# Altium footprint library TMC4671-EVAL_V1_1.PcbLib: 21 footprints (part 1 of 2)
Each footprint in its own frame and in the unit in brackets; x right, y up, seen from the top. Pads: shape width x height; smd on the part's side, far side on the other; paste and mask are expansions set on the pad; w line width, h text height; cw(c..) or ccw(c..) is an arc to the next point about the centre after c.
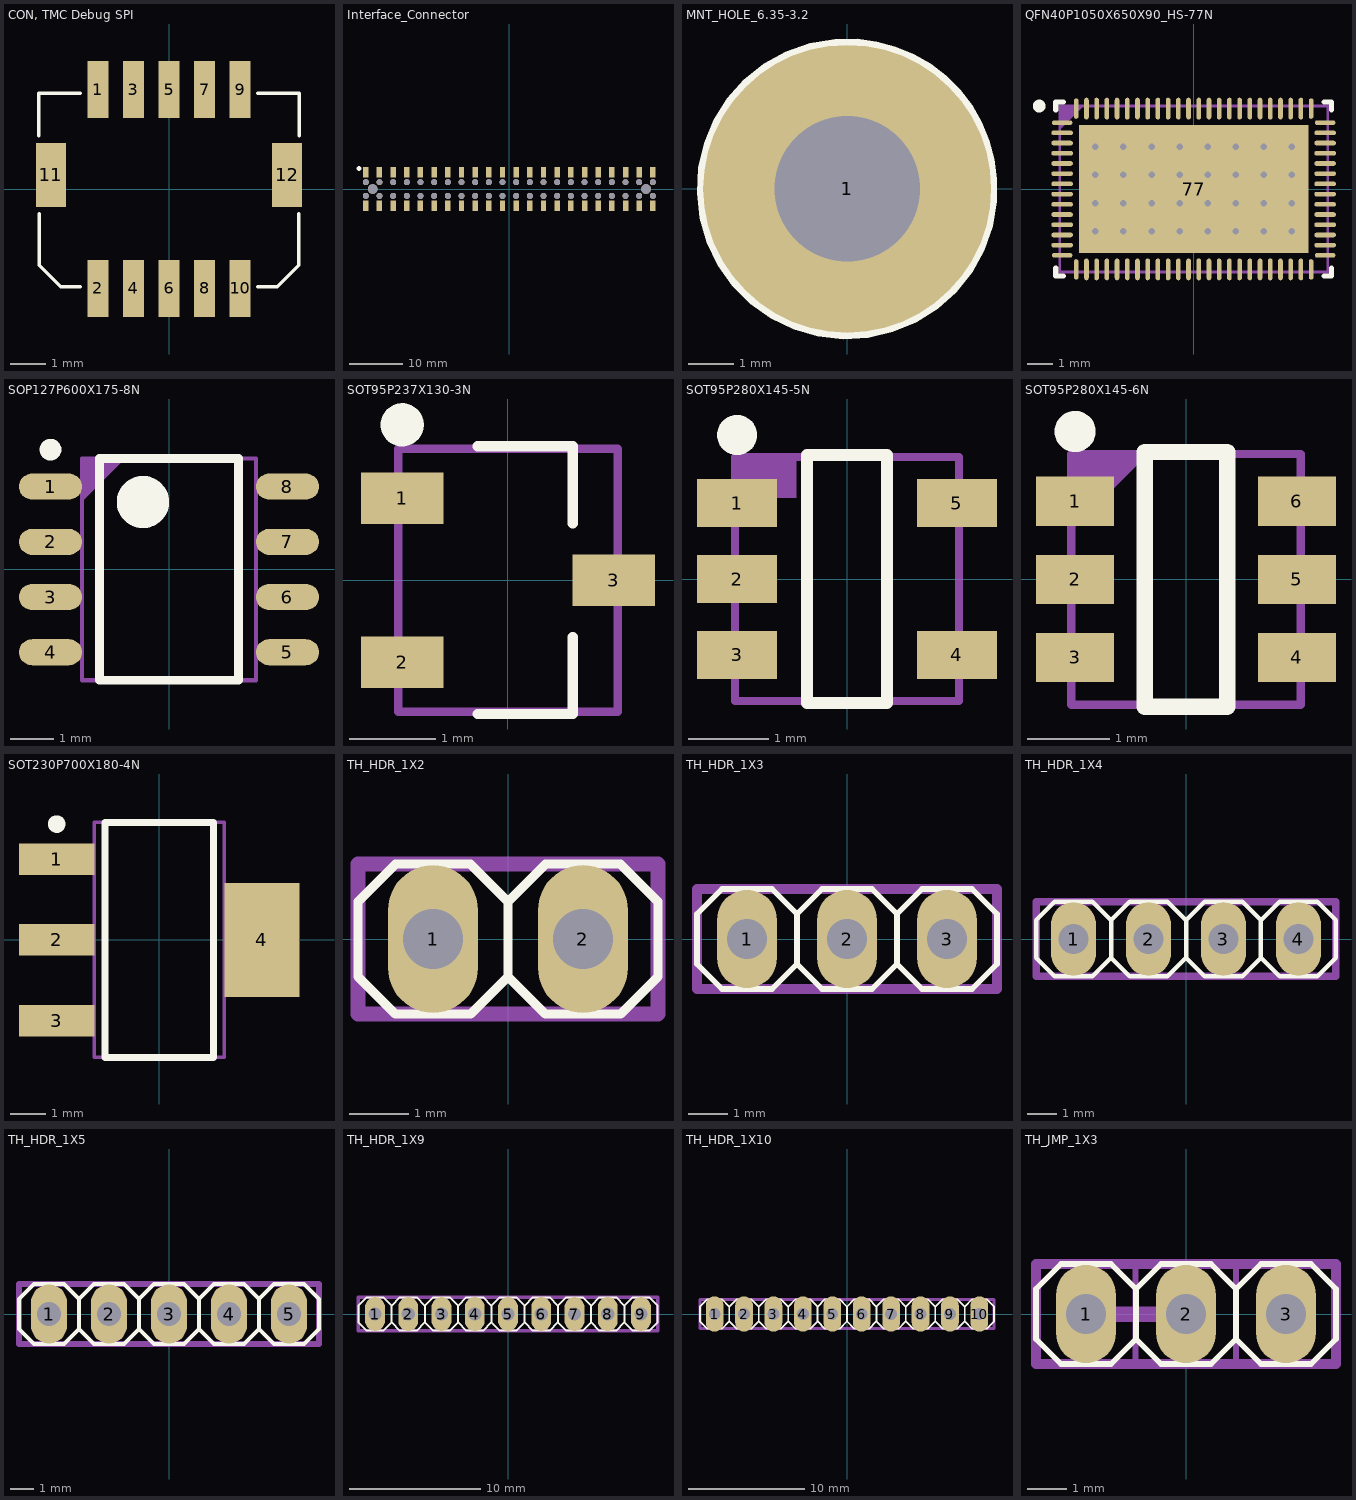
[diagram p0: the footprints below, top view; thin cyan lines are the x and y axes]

## CON, TMC Debug SPI [mm]
pads (12):
  rect 0.6x1.6 smd: 1(-2,2.8) 2(-2,-2.8) 3(-1,2.8) 4(-1,-2.8) 5(0,2.8) 6(0,-2.8) 7(1,2.8) 8(1,-2.8) 9(2,2.8) 10(2,-2.8)
  rect 0.85x1.8 smd: 11(-3.325,0.4) 12(3.325,0.4)
Top Overlay:
  lines w0.1: -3.675,1.5 -3.675,2.7 -2.5,2.7 ; -3.65,-0.7 -3.65,-2.15 -3.05,-2.75 -2.5,-2.75 ; 2.5,-2.75 3.05,-2.75 3.65,-2.15 3.65,-0.7 ; 2.5,2.7 3.675,2.7 3.675,1.5
TopAsm:
  text ".Designator" at -2.589,-0.401 h1
3D body "DF20F-10DP-1V.stp": height 4.6, standoff 0, extent -3.65,-3.225 3.65,3.175

## Interface_Connector [mil]
pads (90):
  rect 40x75 smd: 1(-1050,122.72) 2(-1050,-122.72) 3(-950,122.72) 4(-950,-122.72) 5(-850,122.72) 6(-850,-122.72) 7(-750,122.72) 8(-750,-122.72) 9(-650,122.72) 10(-650,-122.72) 11(-550,122.72) 12(-550,-122.72) 13(-450,122.72) 14(-450,-122.72) 15(-350,122.72) 16(-350,-122.72) 17(-250,122.72) 18(-250,-122.72) 19(-150,122.72) 20(-150,-122.72) 21(-50,122.72) 22(-50,-122.72) 23(50,122.72) 24(50,-122.72) 25(150,122.72) 26(150,-122.72) 27(250,122.72) 28(250,-122.72) 29(350,122.72) 30(350,-122.72) 31(450,122.72) 32(450,-122.72) 33(550,122.72) 34(550,-122.72) 35(650,122.72) 36(650,-122.72) 37(750,122.72) 38(750,-122.72) 39(850,122.72) 40(850,-122.72) 41(950,122.72) 42(950,-122.72) 43(1050,122.72) 44(1050,-122.72)
  round 44 hole 44: HOLE(-1050,-50.28) HOLE(-1050,49.72) HOLE(-950,-50.28) HOLE(-950,49.72) HOLE(-850,-50.28) HOLE(-850,49.72) HOLE(-750,-50.28) HOLE(-750,49.72) HOLE(-650,-50.28) HOLE(-650,49.72) HOLE(-550,-50.28) HOLE(-550,49.72) HOLE(-450,-50.28) HOLE(-450,49.72) HOLE(-350,-50.28) HOLE(-350,49.72) HOLE(-250,-50.28) HOLE(-250,49.72) HOLE(-150,-50.28) HOLE(-150,49.72) HOLE(-50,-50.28) HOLE(-50,49.72) HOLE(50,-50.28) HOLE(50,49.72) HOLE(150,-50.28) HOLE(150,49.72) HOLE(250,-50.28) HOLE(250,49.72) HOLE(350,-50.28) HOLE(350,49.72) HOLE(450,-50.28) HOLE(450,49.72) HOLE(550,-50.28) HOLE(550,49.72) HOLE(650,-50.28) HOLE(650,49.72) HOLE(750,-50.28) HOLE(750,49.72) HOLE(850,-50.28) HOLE(850,49.72) HOLE(950,-50.28) HOLE(950,49.72) HOLE(1050,-50.28) HOLE(1050,49.72)
  round 71 hole 71: HOLE(-1000,-0.28) HOLE(1000,-0.28)
Top Overlay:
  circle w19.68: c-1100,150 r7.07
TopAsm:
  text ".Designator" at -155,-40 h118.11
3D body "HLE-122-02-L-DV.stp": height 143.51, standoff -0.49, extent -1100,-129.49 1100,129.51

## MNT_HOLE_6.35-3.2 [mm]
pads (1):
  round 6.35 hole 3.2: 1(0,0)
Top Overlay:
  pour cut-out: 0,3.302 -0.279,3.302 -0.828,3.209 -1.354,3.025 -1.841,2.755 -2.277,2.408 -2.648,1.993 -2.944,1.521 -3.157,1.006 -3.281,0.463 -3.312,-0.093 -3.25,-0.647 -3.096,-1.182 -2.854,-1.684 -2.532,-2.138 -2.138,-2.532 -1.684,-2.854 -1.182,-3.096 -0.646,-3.25 -0.093,-3.312 0.463,-3.281 1.006,-3.157 1.521,-2.944 1.993,-2.648 2.408,-2.277 2.755,-1.841 3.025,-1.353 3.209,-0.828 3.302,-0.279 3.302,0 3.302,0.216 3.246,0.646 3.133,1.064 2.968,1.464 2.751,1.838 2.488,2.182 2.182,2.488 1.838,2.751 1.464,2.968 1.064,3.134 0.646,3.246 0.216,3.302
Bottom Overlay:
  pour cut-out: 0,3.302 -0.279,3.302 -0.828,3.209 -1.354,3.025 -1.841,2.755 -2.277,2.408 -2.648,1.993 -2.944,1.521 -3.157,1.006 -3.281,0.463 -3.312,-0.093 -3.25,-0.647 -3.096,-1.182 -2.854,-1.684 -2.532,-2.138 -2.138,-2.532 -1.684,-2.854 -1.182,-3.096 -0.646,-3.25 -0.093,-3.312 0.463,-3.281 1.006,-3.157 1.521,-2.944 1.993,-2.648 2.408,-2.277 2.755,-1.841 3.025,-1.353 3.209,-0.828 3.302,-0.279 3.302,0 3.302,0.216 3.246,0.646 3.133,1.064 2.968,1.464 2.751,1.838 2.488,2.182 2.182,2.488 1.838,2.751 1.464,2.968 1.064,3.134 0.646,3.246 0.216,3.302

## QFN40P1050X650X90_HS-77N [mm] "QFN, 76-Leads, Body 10,50x6,50mm, Pitch 0,40mm, Thermal Pad 9,00x5,00mm, IPC Medium Density"
height 0.9
pads (77):
  oval 0.8x0.182 smd mask+0.051: 1(-5.15,2.6) 14(-5.15,-2.6) 39(5.15,-2.6) 52(5.15,2.6)
  oval 0.85x0.182 smd mask+0.051: 2(-5.15,2.2) 3(-5.15,1.8) 4(-5.15,1.4) 5(-5.15,1) 6(-5.15,0.6) 7(-5.15,0.2) 8(-5.15,-0.2) 9(-5.15,-0.6) 10(-5.15,-1) 11(-5.15,-1.4) 12(-5.15,-1.8) 13(-5.15,-2.2) 40(5.15,-2.2) 41(5.15,-1.8) 42(5.15,-1.4) 43(5.15,-1) 44(5.15,-0.6) 45(5.15,-0.2) 46(5.15,0.2) 47(5.15,0.6) 48(5.15,1) 49(5.15,1.4) 50(5.15,1.8) 51(5.15,2.2)
  oval 0.182x0.8 smd mask+0.051: 15(-4.6,-3.15) 38(4.6,-3.15) 53(4.6,3.15) 76(-4.6,3.15)
  oval 0.182x0.85 smd mask+0.051: 16(-4.2,-3.15) 17(-3.8,-3.15) 18(-3.4,-3.15) 19(-3,-3.15) 20(-2.6,-3.15) 21(-2.2,-3.15) 22(-1.8,-3.15) 23(-1.4,-3.15) 24(-1,-3.15) 25(-0.6,-3.15) 26(-0.2,-3.15) 27(0.2,-3.15) 28(0.6,-3.15) 29(1,-3.15) 30(1.4,-3.15) 31(1.8,-3.15) 32(2.2,-3.15) 33(2.6,-3.15) 34(3,-3.15) 35(3.4,-3.15) 36(3.8,-3.15) 37(4.2,-3.15) 54(4.2,3.15) 55(3.8,3.15) 56(3.4,3.15) 57(3,3.15) 58(2.6,3.15) 59(2.2,3.15) 60(1.8,3.15) 61(1.4,3.15) 62(1,3.15) 63(0.6,3.15) 64(0.2,3.15) 65(-0.2,3.15) 66(-0.6,3.15) 67(-1,3.15) 68(-1.4,3.15) 69(-1.8,3.15) 70(-2.2,3.15) 71(-2.6,3.15) 72(-3,3.15) 73(-3.4,3.15) 74(-3.8,3.15) 75(-4.2,3.15)
  rect 9x5 smd: 77(0,0)
via -3.85,1.65 diameter 0.61 hole 0.254
via -2.75,1.65 diameter 0.61 hole 0.254
via -1.65,1.65 diameter 0.61 hole 0.254
via -0.55,1.65 diameter 0.61 hole 0.254
via 0.55,1.65 diameter 0.61 hole 0.254
via 1.65,1.65 diameter 0.61 hole 0.254
via 2.75,1.65 diameter 0.61 hole 0.254
via 3.85,1.65 diameter 0.61 hole 0.254
via -3.85,0.55 diameter 0.61 hole 0.254
via -2.75,0.55 diameter 0.61 hole 0.254
via -1.65,0.55 diameter 0.61 hole 0.254
via -0.55,0.55 diameter 0.61 hole 0.254
via 0.55,0.55 diameter 0.61 hole 0.254
via 1.65,0.55 diameter 0.61 hole 0.254
via 2.75,0.55 diameter 0.61 hole 0.254
via 3.85,0.55 diameter 0.61 hole 0.254
via -3.85,-0.55 diameter 0.61 hole 0.254
via -2.75,-0.55 diameter 0.61 hole 0.254
via -1.65,-0.55 diameter 0.61 hole 0.254
via -0.55,-0.55 diameter 0.61 hole 0.254
via 0.55,-0.55 diameter 0.61 hole 0.254
via 1.65,-0.55 diameter 0.61 hole 0.254
via 2.75,-0.55 diameter 0.61 hole 0.254
via 3.85,-0.55 diameter 0.61 hole 0.254
via -3.85,-1.65 diameter 0.61 hole 0.254
via -2.75,-1.65 diameter 0.61 hole 0.254
via -1.65,-1.65 diameter 0.61 hole 0.254
via -0.55,-1.65 diameter 0.61 hole 0.254
via 0.55,-1.65 diameter 0.61 hole 0.254
via 1.65,-1.65 diameter 0.61 hole 0.254
via 2.75,-1.65 diameter 0.61 hole 0.254
via 3.85,-1.65 diameter 0.61 hole 0.254
Top Overlay:
  circle w0.25: c-6.05,3.25 r0.125
  lines w0.2: -5.4,-3.1 -5.4,-3.4 -5.1,-3.4 ; -5.4,3.1 -5.4,3.4 -5.1,3.4 ; 5.1,-3.4 5.4,-3.4 5.4,-3.1 ; 5.1,3.4 5.4,3.4 5.4,3.1
TopAsm:
  region: -5.25,3.25 -5.25,2.318 -4.318,3.25
  lines w0.1: -5.25,-3.25 5.25,-3.25 5.25,3.25 -5.25,3.25 -5.25,-3.25
  text ".Designator" at -3.014,-0.451 h1
3D body "QFN40P1050X650X90_HS-77N.step": height 0.9, standoff 0, extent -5.251,-3.251 5.251,3.251

## SOP127P600X175-8N [mm] "SOP, 8-Leads, Body 4,92x3,90mm, Pitch 1,27mm, IPC Medium Density"
height 1.75
pads (8):
  oval 1.45x0.6 smd: 1(-2.725,1.905) 2(-2.725,0.635) 3(-2.725,-0.635) 4(-2.725,-1.905) 5(2.725,-1.905) 6(2.725,-0.635) 7(2.725,0.635) 8(2.725,1.905)
Top Overlay:
  circle w0.25: c-2.725,2.755 r0.125
  circle w0.6: c-0.6,1.55 r0.3
  lines w0.2: -1.6,-2.55 -1.6,2.55 1.6,2.55 1.6,-2.55 -1.6,-2.55
TopAsm:
  region: -2,2.55 -2,1.566 -1.016,2.55
  lines w0.1: -2,-2.55 2,-2.55 2,2.55 -2,2.55 -2,-2.55
  text ".Designator" at 0.508,-2.032 h1.27
3D body "SOP127P600X175-8N.step": height 1.75, standoff 0, extent -2.997,-2.55 2.997,2.55

## SOT95P237X130-3N [mm] "SOT23, 3-Leads, Body 2,90x2,37mm, Pitch 0,95mm, IPC Medium Density"
height 1.3
pads (3):
  rect 0.95x0.6 smd: 1(-1.225,0.95) 2(-1.225,-0.95) 3(1.225,0)
Top Overlay:
  circle w0.25: c-1.225,1.8 r0.125
  lines w0.12: -0.35,-1.55 0.75,-1.55 0.75,-0.66 ; -0.35,1.55 0.75,1.55 0.75,0.66
TopAsm:
  lines w0.1: -1.27,-1.524 -1.27,1.524 1.27,1.524 1.27,-1.524 -1.27,-1.524
  text ".Designator" at 0.254,-1.016 h0.76
3D body "SOT95P237X130-3N.step": height 1.3, standoff 0, extent -1.32,-1.55 1.32,1.55

## SOT95P280X145-5N [mm] "SOT23, 5-Leads, Body 2,90x2,80mm, Pitch 0,95mm, IPC Medium Density"
height 1.45
pads (5):
  rect 1x0.6 smd: 1(-1.375,0.95) 2(-1.375,0) 3(-1.375,-0.95) 4(1.375,-0.95) 5(1.375,0.95)
Top Overlay:
  circle w0.25: c-1.375,1.8 r0.125
  lines w0.15: -0.5,-1.55 -0.5,1.55 0.5,1.55 0.5,-1.55 -0.5,-1.55
TopAsm:
  region: -1.397,1.525 -1.397,1.016 -0.635,1.016 -0.635,1.524
  lines w0.1: -1.397,-1.525 -1.397,1.525 1.397,1.525 1.397,-1.525 -1.397,-1.525
  text ".Designator" at 0.451,-1.236 h1
3D body "SOT95P280X145-5N.step": height 1.45, standoff 0, extent -1.5,-1.525 1.5,1.525

## SOT95P280X145-6N [mm] "SOT23, 6-Leads, Body 2,95x2,80mm, Pitch 0,95mm, IPC Medium Density"
height 1.45
pads (6):
  rect 0.95x0.6 smd: 1(-1.35,0.95) 2(-1.35,0) 3(-1.35,-0.95) 4(1.35,-0.95) 5(1.35,0) 6(1.35,0.95)
Top Overlay:
  circle w0.25: c-1.35,1.8 r0.125
  lines w0.2: -0.5,-1.55 0.5,-1.55 0.5,1.55 -0.5,1.55 -0.5,-1.55
TopAsm:
  region: -1.397,1.525 -1.397,0.593 -0.465,1.525
  lines w0.1: -1.397,-1.525 -1.397,1.525 1.397,1.525 1.397,-1.525 -1.397,-1.525
  text ".Designator" at 0.451,-1.236 h1
3D body "SOT95P280X145-6N.step": height 1.45, standoff 0, extent -1.4,-1.55 1.4,1.55

## SOT230P700X180-4N [mm] "SOT223, 4-Leads, Body 6,50x7,00mm (avg), Pitch 2,30mm, IPC Medium Density"
height 1.8
pads (4):
  rect 2.15x0.9 smd: 1(-2.925,2.3) 2(-2.925,0) 3(-2.925,-2.3)
  rect 2.15x3.25 smd: 4(2.925,0)
Top Overlay:
  circle w0.25: c-2.925,3.3 r0.125
  lines w0.2: -1.55,-3.35 -1.55,3.35 1.55,3.35 1.55,-3.35 -1.55,-3.35
TopAsm:
  lines w0.1: -1.85,-3.35 1.85,-3.35 1.85,3.35 -1.85,3.35 -1.85,-3.35
  text ".Designator" at 0.451,-1.998 h1.27
3D body "SOT230P700X180-4N.step": height 1.8, standoff 0, extent -3.5,-3.35 3.5,3.35

## TH_HDR_1X2 [mil]
pads (2):
  oval 60x98.43 hole 40: 1(-50,0) 2(50,0)
Top Overlay:
  lines w6: 0,-25 0,25 ; 0,-25 -25,-50 -75,-50 -100,-25 -100,25 -75,50 -25,50 0,25 ; 0,-25 25,-50 75,-50 100,-25 100,25 75,50 25,50 0,25
TopAsm:
  lines w10: -100,-50 100,-50 99.99,50.01 -100,50 -100,-50
  text ".Designator" at -48.66,-17.76 h39.37
3D body "Pin Header 1x1 TH 2.54mm Pitch.stp": height 351, standoff -99, extent -100.01,-49.99 -0.01,50.01
3D body "Pin Header 1x1 TH 2.54mm Pitch.stp": height 351, standoff -99, extent -0.01,-49.99 99.99,50.01

## TH_HDR_1X3 [mil]
pads (3):
  oval 60x98.43 hole 40: 1(-100,0) 2(0,0) 3(100,0)
Top Overlay:
  lines w6: -50,-25 -25,-50 25,-50 50,-25 ; -50,-25 -75,-50 -125,-50 -150,-25 -150,25 -125,50 -75,50 -50,25 ; -50,-25 -50,25 ; -50,25 -25,50 25,50 50,25 ; 50,-25 75,-50 125,-50 150,-25 150,25 125,50 75,50 50,25 ; 50,-25 50,25
TopAsm:
  lines w10: -150,-50 -150,50 150,50 150,-50 -150,-50
  text ".Designator" at -98.66,-17.76 h39.37
3D body "Pin Header 1x1 TH 2.54mm Pitch.stp": height 351, standoff -99, extent 49.99,-49.99 149.99,50.01
3D body "Pin Header 1x1 TH 2.54mm Pitch.stp": height 351, standoff -99, extent -50.01,-49.99 49.99,50.01
3D body "Pin Header 1x1 TH 2.54mm Pitch.stp": height 351, standoff -99, extent -150.01,-49.99 -50.01,50.01

## TH_HDR_1X4 [mil]
pads (4):
  oval 60x98.43 hole 40: 1(-150,0) 2(-50,0) 3(50,0) 4(150,0)
Top Overlay:
  lines w6: -100,-25 -100,25 ; -100,-25 -125,-50 -175,-50 -200,-25 -200,25 -175,50 -125,50 -100,25 ; -100,-25 -75,-50 -25,-50 0,-25 ; -100,25 -75,50 -25,50 0,25 ; 0,-25 0,25 ; 0,-25 25,-50 75,-50 100,-25 ; 0,25 25,50 75,50 100,25 ; 100,-25 100,25 ; 100,-25 125,-50 175,-50 200,-25 200,25 175,50 125,50 100,25 ; 100,-25 100,25
Mechanical 18:
  rectangle: 40,-10 60,10
  rectangle: -160,-10 -140,10
  rectangle: -60,-10 -40,10
TopAsm:
  lines w10: -200,-50 -200,50 200,50 200,-50 -200,-50
  text ".Designator" at -148.66,-17.76 h39.37
3D body "Pin Header 1x1 TH 2.54mm Pitch.stp": height 351, standoff -99, extent -200.01,-49.99 -100.01,50.01
3D body "Pin Header 1x1 TH 2.54mm Pitch.stp": height 351, standoff -99, extent -100.01,-49.99 -0.01,50.01
3D body "Pin Header 1x1 TH 2.54mm Pitch.stp": height 351, standoff -99, extent -0.01,-49.99 99.99,50.01
3D body "Pin Header 1x1 TH 2.54mm Pitch.stp": height 351, standoff -99, extent 99.99,-49.99 199.99,50.01

## TH_HDR_1X5 [mil]
pads (5):
  oval 60x98.43 hole 40: 1(-200,0) 2(-100,0) 3(0,0) 4(100,0) 5(200,0)
Top Overlay:
  lines w6: -150,-25 -125,-50 -75,-50 -50,-25 ; -150,-25 -175,-50 -225,-50 -250,-25 -250,25 -225,50 -175,50 -150,25 ; -150,-25 -150,25 ; -150,25 -125,50 -75,50 -50,25 ; -50,-25 -25,-50 25,-50 50,-25 ; -50,-25 -50,25 ; -50,25 -25,50 25,50 50,25 ; 50,-25 50,25 ; 50,-25 75,-50 125,-50 150,-25 ; 50,-25 50,25 ; 50,25 75,50 125,50 150,25 ; 150,-25 150,25 ; 150,-25 175,-50 225,-50 250,-25 250,25 225,50 175,50 150,25 ; 150,-25 150,25 ; 150,-25 150,25
TopAsm:
  lines w10: -250,-50 250,-50 250,50 -250,50 -250,-50
  text ".Designator" at -198.66,-17.76 h39.37
3D body "Pin Header 1x1 TH 2.54mm Pitch.stp": height 351, standoff -99, extent 149.99,-49.99 249.99,50.01
3D body "Pin Header 1x1 TH 2.54mm Pitch.stp": height 351, standoff -99, extent 49.99,-49.99 149.99,50.01
3D body "Pin Header 1x1 TH 2.54mm Pitch.stp": height 351, standoff -99, extent -50.01,-49.99 49.99,50.01
3D body "Pin Header 1x1 TH 2.54mm Pitch.stp": height 351, standoff -99, extent -150.01,-49.99 -50.01,50.01
3D body "Pin Header 1x1 TH 2.54mm Pitch.stp": height 351, standoff -99, extent -250.01,-49.99 -150.01,50.01

## TH_HDR_1X9 [mil]
pads (9):
  oval 60x102.36 hole 40: 1(-400,0) 2(-300,0) 3(-200,0) 4(-100,0) 5(0,0) 6(100,0) 7(200,0) 8(300,0) 9(400,0)
Top Overlay:
  lines w6: -350,-25 -325,-50 -275,-50 -250,-25 ; -350,-25 -375,-50 -425,-50 -450,-25 -450,25 -425,50 -375,50 -350,25 ; -350,-25 -350,25 ; -350,25 -325,50 -275,50 -250,25 ; -250,-25 -225,-50 -175,-50 -150,-25 ; -250,-25 -250,25 ; -250,25 -225,50 -175,50 -150,25 ; -150,-25 -150,25 ; -150,-25 -125,-50 -75,-50 -50,-25 ; -150,-25 -150,25 ; -150,25 -125,50 -75,50 -50,25 ; -50,-25 -50,25 ; -50,-25 -25,-50 25,-50 50,-25 ; -50,-25 -50,25 ; -50,-25 -50,25 ; -50,25 -25,50 25,50 50,25 ; 50,-25 50,25 ; 50,-25 75,-50 125,-50 150,-25 ; 50,-25 50,25 ; 50,25 75,50 125,50 150,25 ; 150,-25 150,25 ; 150,-25 175,-50 225,-50 250,-25 ; 150,-25 150,25 ; 150,25 175,50 225,50 250,25 ; 250,-25 250,25 ; 250,-25 250,25 ; 250,-25 275,-50 325,-50 350,-25 ; 250,-25 250,25 ; 250,25 275,50 325,50 350,25 ; 350,-25 350,25 ; 350,-25 375,-50 425,-50 450,-25 450,25 425,50 375,50 350,25 ; 350,-25 350,25 ; 350,-25 350,25 ; 350,-25 350,25
Mechanical 18:
  rectangle: -310,-10 -290,10
  rectangle: -410,-10 -390,10
  rectangle: -210,-10 -190,10
TopAsm:
  lines w10: -450,-50 449.99,-50 450,50 -450,50 -450,-50
  text ".Designator" at -198.66,-17.76 h39.37
3D body "Pin Header 1x1 TH 2.54mm Pitch.stp": height 351, standoff -99, extent 349.99,-49.99 449.99,50.01
3D body "Pin Header 1x1 TH 2.54mm Pitch.stp": height 351, standoff -99, extent 49.99,-49.99 149.99,50.01
3D body "Pin Header 1x1 TH 2.54mm Pitch.stp": height 351, standoff -99, extent 149.99,-49.99 249.99,50.01
3D body "Pin Header 1x1 TH 2.54mm Pitch.stp": height 351, standoff -99, extent 249.99,-49.99 349.99,50.01
3D body "Pin Header 1x1 TH 2.54mm Pitch.stp": height 351, standoff -99, extent -50.01,-49.99 49.99,50.01
3D body "Pin Header 1x1 TH 2.54mm Pitch.stp": height 351, standoff -99, extent -150.01,-49.99 -50.01,50.01
3D body "Pin Header 1x1 TH 2.54mm Pitch.stp": height 351, standoff -99, extent -250.01,-49.99 -150.01,50.01
3D body "Pin Header 1x1 TH 2.54mm Pitch.stp": height 351, standoff -99, extent -350.01,-49.99 -250.01,50.01
3D body "Pin Header 1x1 TH 2.54mm Pitch.stp": height 351, standoff -99, extent -450.01,-49.99 -350.01,50.01

## TH_HDR_1X10 [mil]
pads (10):
  oval 60x120 hole 40: 1(-450,0) 2(-350,0) 3(-250,0) 4(-150,0) 5(-50,0) 6(50,0) 7(150,0) 8(250,0) 9(350,0) 10(450,0)
Top Overlay:
  lines w6: -400,-25 -375,-50 -325,-50 -300,-25 ; -400,-25 -425,-50 -475,-50 -500,-25 -500,25 -475,50 -425,50 -400,25 ; -400,-25 -400,25 ; -400,25 -375,50 -325,50 -300,25 ; -300,-25 -275,-50 -225,-50 -200,-25 ; -300,-25 -300,25 ; -300,25 -275,50 -225,50 -200,25 ; -200,-25 -200,25 ; -200,-25 -175,-50 -125,-50 -100,-25 ; -200,-25 -200,25 ; -200,25 -175,50 -125,50 -100,25 ; -100,-25 -100,25 ; -100,-25 -75,-50 -25,-50 0,-25 ; -100,-25 -100,25 ; -100,-25 -100,25 ; -100,25 -75,50 -25,50 0,25 ; 0,-25 0,25 ; 0,-25 25,-50 75,-50 100,-25 ; 0,-25 0,25 ; 0,25 25,50 75,50 100,25 ; 100,-25 100,25 ; 100,-25 125,-50 175,-50 200,-25 ; 100,-25 100,25 ; 100,25 125,50 175,50 200,25 ; 200,-25 200,25 ; 200,-25 200,25 ; 200,-25 225,-50 275,-50 300,-25 ; 200,-25 200,25 ; 200,25 225,50 275,50 300,25 ; 300,-25 300,25 ; 300,-25 325,-50 375,-50 400,-25 ; 300,-25 300,25 ; 300,-25 300,25 ; 300,-25 300,25 ; 300,25 325,50 375,50 400,25 ; 400,-25 400,25 ; 400,-25 400,25 ; 400,-25 400,25 ; 400,-25 400,25 ; 400,-25 425,-50 475,-50 500,-25 500,25 475,50 425,50 400,25 ; 400,-25 400,25
Mechanical 18:
  rectangle: -360,-10 -340,10
  rectangle: -460,-10 -440,10
  rectangle: -260,-10 -240,10
TopAsm:
  lines w10: -500,-50 499.99,-50 500,50 -500,50 -500,-50
  text ".Designator" at -248.66,-17.76 h39.37
3D body "Pin Header 1x1 TH 2.54mm Pitch.stp": height 351, standoff -99, extent 299.99,-49.99 399.99,50.01
3D body "Pin Header 1x1 TH 2.54mm Pitch.stp": height 351, standoff -99, extent -0.01,-49.99 99.99,50.01
3D body "Pin Header 1x1 TH 2.54mm Pitch.stp": height 351, standoff -99, extent 99.99,-49.99 199.99,50.01
3D body "Pin Header 1x1 TH 2.54mm Pitch.stp": height 351, standoff -99, extent 199.99,-49.99 299.99,50.01
3D body "Pin Header 1x1 TH 2.54mm Pitch.stp": height 351, standoff -99, extent -100.01,-49.99 -0.01,50.01
3D body "Pin Header 1x1 TH 2.54mm Pitch.stp": height 351, standoff -99, extent -200.01,-49.99 -100.01,50.01
3D body "Pin Header 1x1 TH 2.54mm Pitch.stp": height 351, standoff -99, extent -300.01,-49.99 -200.01,50.01
3D body "Pin Header 1x1 TH 2.54mm Pitch.stp": height 351, standoff -99, extent -400.01,-49.99 -300.01,50.01
3D body "Pin Header 1x1 TH 2.54mm Pitch.stp": height 351, standoff -99, extent -500.01,-49.99 -400.01,50.01
3D body "Pin Header 1x1 TH 2.54mm Pitch.stp": height 351, standoff -99, extent 399.99,-49.99 499.99,50.01

## TH_JMP_1X3 [mil]
pads (3):
  oval 60x98.43 hole 40: 1(-100,0) 2(0,0) 3(100,0)
Top Overlay:
  lines w6: -50,-25 -25,-50 25,-50 50,-25 ; -50,-25 -75,-50 -125,-50 -150,-25 -150,25 -125,50 -75,50 -50,25 ; -50,-25 -50,25 ; -50,25 -25,50 25,50 50,25 ; 50,-25 75,-50 125,-50 150,-25 150,25 125,50 75,50 50,25 ; 50,-25 50,25
TopAsm:
  drawing of 31 lines, arcs and shapes, not listed
  text ".Designator" at -100,100 h39.37
3D body "User Library-SHORTING JUMPER.step": height 356.14, standoff 123.86, extent -150,-49.99 50,50.01
3D body "Pin Header 1x1 TH 2.54mm Pitch.stp": height 351, standoff -99, extent 49.99,-49.99 149.99,50.01
3D body "Pin Header 1x1 TH 2.54mm Pitch.stp": height 351, standoff -99, extent -50.01,-49.99 49.99,50.01
3D body "Pin Header 1x1 TH 2.54mm Pitch.stp": height 351, standoff -99, extent -150.01,-49.99 -50.01,50.01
